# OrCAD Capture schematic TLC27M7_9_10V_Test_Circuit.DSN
size A; title: LinCMOS™ PRECISION QUAD OPERATIONAL AMPLIFIERS; rev: 1.1; note: Datasheet: SLOS093D EVM: N/A
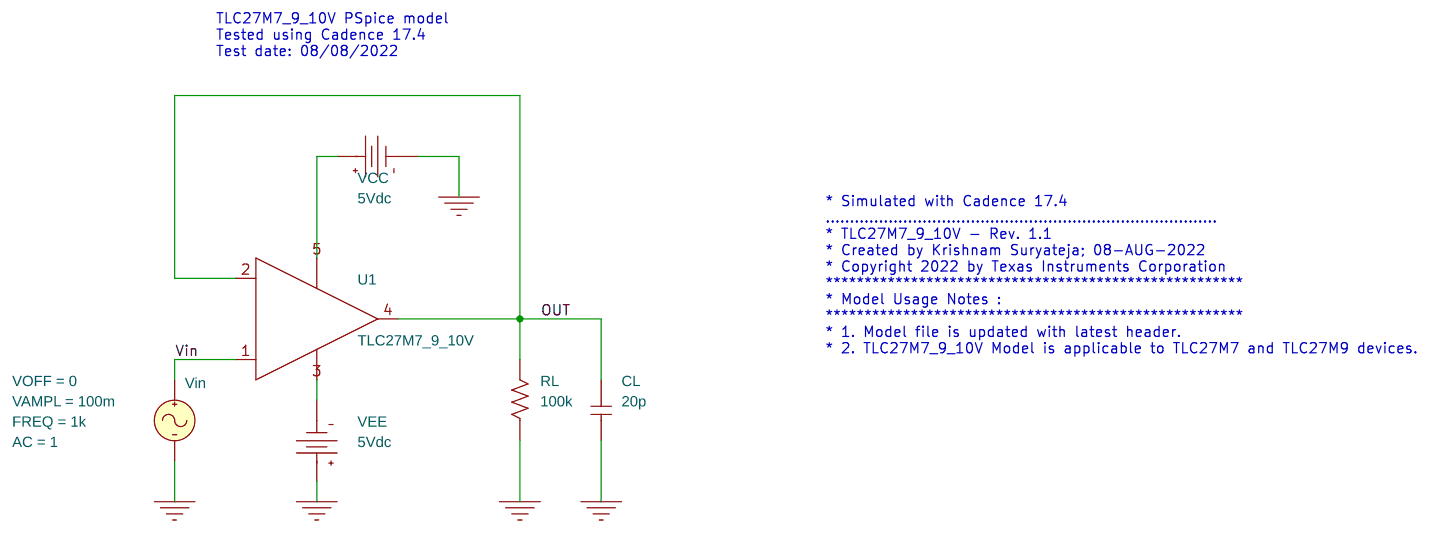
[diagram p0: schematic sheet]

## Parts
CL  20p  [RAD/CK05]
RL  100k  [AX/RC05]
U1  TLC27M7_9_10V
VCC  VDC
VEE  VDC
Vin  VSIN

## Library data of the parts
CL = C
RL = R
U1 = TLC27M7_9_10V
VCC VEE = VDC: DC: 5Vdc
Vin = VSIN: AC: 1; FREQ: 1k; VAMPL: 100m; VOFF: 0

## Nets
Vin: U1.1(+) Vin.1(+)
0: CL.1 RL.1 VCC.1(-) VEE.0(+) Vin.2(-)
OUT: CL.2 RL.2 U1.2(-) U1.4(OUT)
N22995: U1.5(V+) VCC.0(+)
N37251: U1.3(V-) VEE.1(-)

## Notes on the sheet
- TLC27M7_9_10V PSpice model
  Tested using Cadence 17.4
  Test date: 08/08/2022
- * Simulated with Cadence 17.4
  .................................................................................
  * TLC27M7_9_10V - Rev. 1.1
  * Created by Krishnam Suryateja; 08-AUG-2022
  * Copyright 2022 by Texas Instruments Corporation
  ******************************************************
  * Model Usage Notes :
  ******************************************************
  * 1. Model file is updated with latest header.
  * 2. TLC27M7_9_10V Model is applicable to TLC27M7 and TLC27M9 devices.
